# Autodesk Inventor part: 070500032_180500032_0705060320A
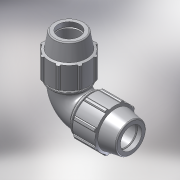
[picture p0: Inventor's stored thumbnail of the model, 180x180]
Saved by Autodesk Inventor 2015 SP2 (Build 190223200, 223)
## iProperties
Created: 2017-02
Part Number: 070500032_180500032_0705060320A
Material: PVC-Piping
Description: PLASSON 90° ELBOW 32-32
Document SubType Name: Modeling
Designer: KIM
Mass: 92.6774 g
Surface Area: 199.44 cm^2
Volume: 66.1981 cm^3
Density: 1.4 g/cm^3
Appearance: Smooth - White
Author: KIM
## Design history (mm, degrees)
derived "07050.ipt"
feature "Solid1::07050.ipt"
tag "TaggingFeature1"
body "Solid1"
other parameters: "d2" = 32, "d4" = 7.75, "d5" = 23.25, "d7" = 64, "d9" = 13.28571, "d11" = 3.1, "d13" = 120 deg, "d14" = 44.8, "d15" = 10 deg, "d16" = 55.68, "d18" = 1.6, "d19" = 35 deg, "d20" = 17.5 deg, "d21" = 59.52, "d23" = 0, "d25" = 360 deg, "d27" = 1.28, "d33" = 0.64, "d42" = 34.41, "d43" = 1.92, "d46" = 0.96, "d51" = 93, "d59" = 90 deg, "d63" = 67, "d64" = 28.8, "d67" = 48, "d68" = 3.1, "d70" = 90 deg, "d71" = 4.8, "d_" = 32, "E_" = 64, "A_" = 93, "l_" = 67
